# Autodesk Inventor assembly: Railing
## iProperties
Created: 2006-02
Part Number: Railing
Document SubType Name: Assembly
Designer: 40664
CSToolsMass: 29.0
CSToolsVolume: 28892833.0
CSToolsArea: 153661.0
Author: 40664
